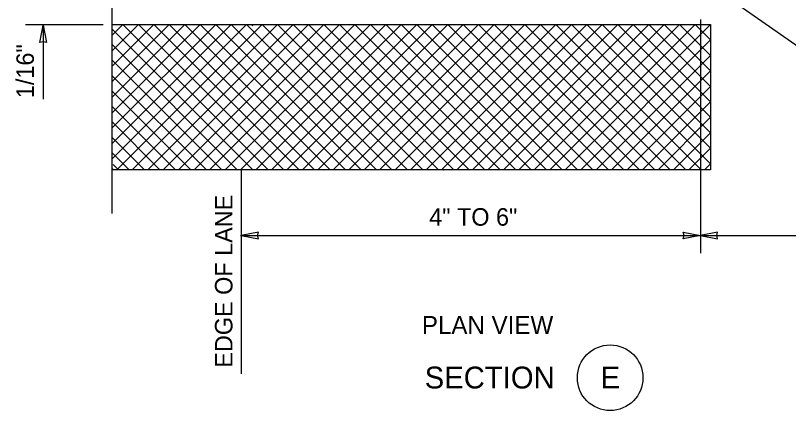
# Model space of a CAD drawing. Extents: x 99862 to 103151, y 100000 to 108076.
# Drawn here: x 101476 to 102183, y 104053 to 104414 of the extents above; entities that cross this region are included whole.
import ezdxf

# ---------------------------------------------------------------- set-up
doc = ezdxf.new("R2010")
doc.units = 0
for name, color, linetype in [('Level 15', 7, 'Continuous'), ('Level 18', 7, 'Continuous'), ('Level 2', 7, 'Continuous'), ('Level 20', 7, 'Continuous'), ('Level 6', 7, 'Continuous'), ('Level 9', 7, 'Continuous')]:
    doc.layers.add(name, color=color, linetype=linetype)

msp = doc.modelspace()

# ---------------------------------------------------------------- linework, layer by layer
at = {"layer": 'Level 15'}
for p, q in [((102092.62, 104455.31), (102217.94, 104367.63)), ((101556.48, 104405.54), (101485.71, 104405.54)), ((102102.78, 104410.44), (102102.78, 104196.69)), ((101501.71, 104404.98), (101501.71, 104337.53)), ((101682.29, 104212.69), (102102.78, 104212.69)), ((102102.79, 104212.69), (102354.74, 104212.69))]:
    msp.add_line(p, q, dxfattribs=at)
msp.add_lwpolyline([(101564.48, 104758.86), (101564.48, 104526.29), (101595.46, 104526.29), (101533.51, 104464.35), (101564.48, 104464.35), (101564.48, 104232.89)], dxfattribs=at)
for points in [[(101501.71, 104405.01), (101504.79, 104389.29), (101501.71, 104390.02), (101498.63, 104389.29)], [(101682.84, 104212.69), (101698.56, 104209.6), (101697.84, 104212.69), (101698.56, 104215.77)], [(102102.78, 104212.69), (102087.05, 104209.6), (102087.78, 104212.69), (102087.05, 104215.77)], [(102102.79, 104212.69), (102118.52, 104209.6), (102117.79, 104212.69), (102118.52, 104215.77)]]:
    msp.add_lwpolyline(points, close=True, dxfattribs=at)
at = {"layer": 'Level 18'}
msp.add_lwpolyline([(101564.48, 104405.72), (102112.06, 104405.72), (102112.06, 104272.81), (101564.48, 104272.81)], dxfattribs=at)
at = {"layer": 'Level 2'}
msp.add_line((101682.84, 104272.48), (101682.84, 104086.18), dxfattribs=at)
at = {"layer": 'Level 6'}
for p, q in [((101564.53, 104282.45), (101687.79, 104405.72)), ((101564.59, 104296.66), (101673.65, 104405.72)), ((101564.66, 104310.87), (101659.51, 104405.72)), ((101564.73, 104325.08), (101645.37, 104405.72)), ((101564.79, 104339.29), (101631.22, 104405.72)), ((101564.86, 104353.5), (101617.08, 104405.72)), ((101564.93, 104367.71), (101602.94, 104405.72)), ((101564.99, 104381.91), (101588.8, 104405.72)), ((101565.06, 104396.12), (101574.65, 104405.72)), ((101565.1, 104405.72), (101565.1, 104405.72)), ((101565.1, 104405.72), (101565.1, 104405.72)), ((101569.03, 104272.81), (101701.93, 104405.72)), ((101574.65, 104405.72), (101707.56, 104272.81)), ((101583.17, 104272.81), (101716.08, 104405.72)), ((101588.8, 104405.72), (101721.7, 104272.81)), ((101597.32, 104272.81), (101730.22, 104405.72)), ((101602.94, 104405.72), (101735.84, 104272.81)), ((101611.46, 104272.81), (101744.36, 104405.72)), ((101617.08, 104405.72), (101749.98, 104272.81)), ((101625.6, 104272.81), (101758.5, 104405.72)), ((101631.22, 104405.72), (101764.13, 104272.81)), ((101639.74, 104272.81), (101772.64, 104405.72)), ((101645.37, 104405.72), (101778.27, 104272.81)), ((101653.88, 104272.81), (101786.79, 104405.72)), ((101659.51, 104405.72), (101792.41, 104272.81)), ((101668.03, 104272.81), (101800.93, 104405.72)), ((101673.65, 104405.72), (101806.55, 104272.81)), ((101682.17, 104272.81), (101815.07, 104405.72)), ((101687.79, 104405.72), (101820.69, 104272.81)), ((101692.38, 104405.72), (101693.56, 104404.54)), ((101696.31, 104272.81), (101829.21, 104405.72)), ((101701.93, 104405.72), (101834.84, 104272.81)), ((101706.12, 104405.32), (101706.53, 104405.72)), ((101706.53, 104405.72), (101706.88, 104405.36)), ((101710.45, 104272.81), (101843.36, 104405.72)), ((101716.08, 104405.72), (101848.98, 104272.81)), ((101724.59, 104272.81), (101857.5, 104405.72)), ((101730.22, 104405.72), (101863.12, 104272.81)), ((101738.74, 104272.81), (101871.64, 104405.72)), ((101744.36, 104405.72), (101877.26, 104272.81)), ((101752.88, 104272.81), (101885.78, 104405.72)), ((101758.5, 104405.72), (101891.41, 104272.81)), ((101767.02, 104272.81), (101899.92, 104405.72)), ((101772.64, 104405.72), (101905.55, 104272.81)), ((101781.16, 104272.81), (101914.07, 104405.72)), ((101786.79, 104405.72), (101919.69, 104272.81)), ((101795.3, 104272.81), (101928.21, 104405.72)), ((101800.93, 104405.72), (101933.83, 104272.81)), ((101809.45, 104272.81), (101942.35, 104405.72)), ((101815.07, 104405.72), (101947.97, 104272.81)), ((101823.59, 104272.81), (101956.49, 104405.72)), ((101829.21, 104405.72), (101962.12, 104272.81)), ((101837.73, 104272.81), (101970.63, 104405.72)), ((101843.36, 104405.72), (101976.26, 104272.81)), ((101851.87, 104272.81), (101984.78, 104405.72)), ((101857.5, 104405.72), (101990.4, 104272.81)), ((101866.02, 104272.81), (101998.92, 104405.72)), ((101871.64, 104405.72), (102004.54, 104272.81)), ((101880.16, 104272.81), (102013.06, 104405.72)), ((101885.78, 104405.72), (102018.68, 104272.81)), ((101894.3, 104272.81), (102027.2, 104405.72)), ((101899.92, 104405.72), (102032.83, 104272.81)), ((101908.44, 104272.81), (102041.34, 104405.72)), ((101914.07, 104405.72), (102046.97, 104272.81)), ((101922.58, 104272.81), (102055.49, 104405.72)), ((101928.21, 104405.72), (102061.11, 104272.81)), ((101936.73, 104272.81), (102069.63, 104405.72)), ((101942.35, 104405.72), (102075.25, 104272.81)), ((101950.87, 104272.81), (102083.77, 104405.72)), ((101956.49, 104405.72), (102089.4, 104272.81)), ((101965.01, 104272.81), (102097.91, 104405.72)), ((101970.63, 104405.72), (102103.54, 104272.81)), ((101979.15, 104272.81), (102112.06, 104405.72)), ((101984.78, 104405.72), (102112.06, 104278.44)), ((101998.92, 104405.72), (102112.06, 104292.58)), ((102013.06, 104405.72), (102112.06, 104306.72)), ((102027.2, 104405.72), (102112.06, 104320.86)), ((102041.34, 104405.72), (102112.06, 104335.01)), ((102055.49, 104405.72), (102112.06, 104349.15)), ((102069.63, 104405.72), (102112.06, 104363.29)), ((102083.77, 104405.72), (102112.06, 104377.43)), ((102097.91, 104405.72), (102112.06, 104391.58)), ((102102.51, 104405.72), (102102.78, 104405.45)), ((102112.06, 104405.72), (102112.06, 104405.72)), ((102112.06, 104405.72), (102112.06, 104405.72)), ((101565.08, 104401.15), (101693.42, 104272.81)), ((101993.29, 104272.81), (102112.06, 104391.58)), ((101565.02, 104387.07), (101679.27, 104272.81)), ((102007.44, 104272.81), (102112.06, 104377.43)), ((101564.95, 104372.99), (101665.13, 104272.81)), ((102021.58, 104272.81), (102112.06, 104363.29)), ((101564.89, 104358.92), (101650.99, 104272.81)), ((102035.72, 104272.81), (102112.06, 104349.15)), ((101564.82, 104344.84), (101636.85, 104272.81)), ((102049.86, 104272.81), (102112.06, 104335.01)), ((101564.75, 104330.76), (101622.7, 104272.81)), ((102064.01, 104272.81), (102112.06, 104320.86)), ((101564.69, 104316.69), (101608.56, 104272.81)), ((102078.15, 104272.81), (102112.06, 104306.72)), ((101564.62, 104302.61), (101594.42, 104272.81)), ((102092.29, 104272.81), (102112.06, 104292.58)), ((101564.56, 104288.54), (101580.28, 104272.81)), ((102106.43, 104272.81), (102112.06, 104278.44)), ((101564.49, 104274.46), (101566.14, 104272.81)), ((101565.84, 104277.71), (101570.73, 104272.81)), ((101867.65, 104272.88), (101867.71, 104272.81))]:
    msp.add_line(p, q, dxfattribs=at)
at = {"layer": 'Level 9'}
msp.add_circle((102020.22, 104082.72), 30, dxfattribs=at)

# ---------------------------------------------------------------- texts
at = {"layer": 'Level 20'}
for s, rotation, p in [('1/16"', 90.00001, (101493.24, 104338.39)), ('EDGE OF LANE', 90, (101674.84, 104091.91)), ('4" TO 6"', 359.99999, (101854.75, 104221.75))]:
    msp.add_text(s, height=16, rotation=rotation, dxfattribs=at).set_placement(p)
for s, height, p in [('PLAN VIEW', 16.5, (101848.04, 104122.65)), ('SECTION', 20, (101850.63, 104072.9)), ('E', 20, (102011.52, 104072.9))]:
    msp.add_text(s, height=height, dxfattribs=at).set_placement(p)

doc.saveas('drawing.dxf')
